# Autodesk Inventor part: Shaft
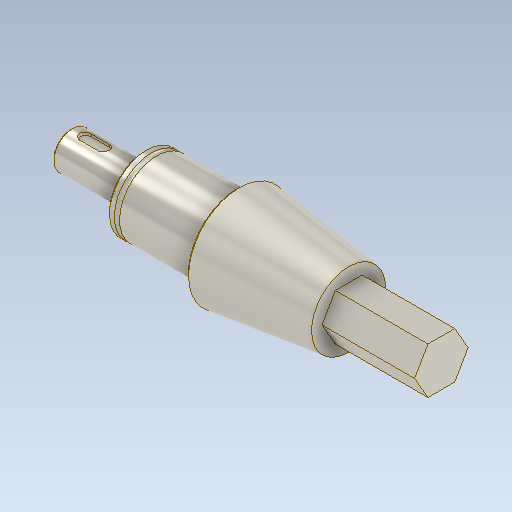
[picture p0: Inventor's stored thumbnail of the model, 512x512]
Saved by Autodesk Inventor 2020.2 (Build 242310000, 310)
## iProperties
Created: 2020-01
Part Number: Shaft
Material: Titanium
Document SubType Name: Modeling
Designer: thira
Density: 4.51 g/cm^3
Appearance: Titanium
CustomPartVersion: 1
Author: thira
Length: 400.000 mm
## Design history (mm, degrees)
sketch "Main Sketch"
  geometry: L1 (0, 0)-(400, 0) reference; L2 (0, 0)-(0, 20); L3 (0, 20)-(80, 20); L4 (80, 20)-(80, 40); L5 (80, 40)-(180, 40); L6 (180, 40)-(180, 55); L7 (300, 40)-(300, 28.868); L8 (180, 55)-(300, 40); L9 (400, 28.868)-(400, 0); L10 (300, 28.868)-(400, 28.868)
  constraints: 20 end point, 5 horizontal, 5 vertical
  dimensions: "d3" = 40 diameter of L3 L1 (derived); "d4" = 80 diameter of L5 L1 (derived); "d5" = 57.73503 diameter of L10 L1 (derived)
revolve "Revolution1" sketch "Main Sketch" stored, may be unused: angle "d6" = 0 deg
chamfer "Chamfer1" distance "d7" = 2; stored, may be unused: second distance "d8" = 2, angle "d9" = 45 deg
fillet "Fillet1" dims "d10" = 2
node "Keyway1"
chamfer "Chamfer2" distance "d11" = 2; stored, may be unused: second distance "d12" = 2, angle "d13" = 45 deg
fillet "Fillet2" dims "d14" = 2
node "Groove1"
chamfer "Chamfer3" distance "d15" = 2; stored, may be unused: second distance "d16" = 2, angle "d17" = 45 deg
node "N-Side1"
body "Solid1"
feature "iFeature3:1"
feature "iFeature1:1"
feature "iFeature1:2"
other parameters: "d0" = 0, "d1" = 0, "d2" = 0, "Length" = 400 [user parameter]
